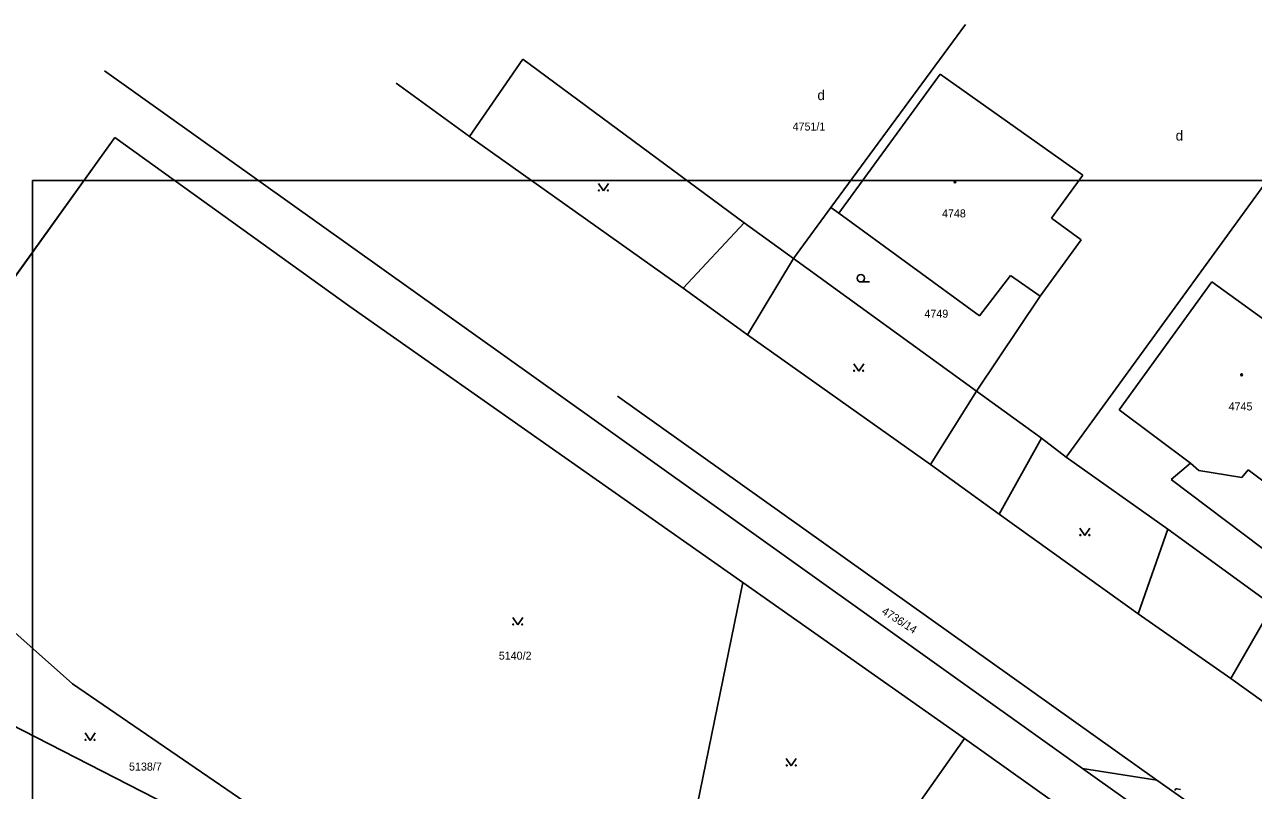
# Model space of a CAD drawing. Extents: x -400488 to -400124, y -1251493 to -1251223.
# Drawn here: x -400397.9 to -400324.2, y -1251269.6 to -1251223.7 of the extents above; entities that cross this region are included whole.
import ezdxf

# ---------------------------------------------------------------- set-up
doc = ezdxf.new("R2010")
doc.units = 0
doc.layers.add('Level 3', color=7, linetype='Continuous')
doc.layers.add('Level 63', color=7, linetype='Continuous')

msp = doc.modelspace()

# ---------------------------------------------------------------- linework, layer by layer
at = {"layer": 'Level 3'}
msp.add_lwpolyline([(-400397.431, -1251233.087), (-400250.431, -1251233.087), (-400250.431, -1251440.987), (-400397.431, -1251440.987)], close=True, dxfattribs=at)
at = {"layer": 'Level 63'}
for p, q in [((-400341.49, -1251223.74), (-400349.56, -1251234.71)), ((-400349.56, -1251234.71), (-400341.49, -1251223.74)), ((-400371.24, -1251230.44), (-400368.03, -1251225.82)), ((-400354.77, -1251235.63), (-400368.03, -1251225.82)), ((-400368.03, -1251225.82), (-400354.77, -1251235.63)), ((-400363.63, -1251247.54), (-400393.13, -1251226.52)), ((-400393.13, -1251226.52), (-400363.63, -1251247.54)), ((-400349.1, -1251235.04), (-400343.01, -1251226.71)), ((-400343.01, -1251226.71), (-400334.46, -1251232.77)), ((-400371.24, -1251230.44), (-400375.63, -1251227.25)), ((-400375.63, -1251227.25), (-400371.24, -1251230.44)), ((-400407.88, -1251251.89), (-400392.51, -1251230.5)), ((-400392.51, -1251230.5), (-400407.88, -1251251.89)), ((-400392.51, -1251230.5), (-400378.41, -1251240.64)), ((-400378.41, -1251240.64), (-400392.51, -1251230.5)), ((-400358.43, -1251239.54), (-400371.24, -1251230.44)), ((-400371.24, -1251230.44), (-400358.43, -1251239.54)), ((-400335.45, -1251249.68), (-400321.67, -1251230.69)), ((-400321.67, -1251230.69), (-400335.45, -1251249.68)), ((-400334.46, -1251232.77), (-400336.34, -1251235.35)), ((-400363.51, -1251233.26), (-400363.21, -1251233.71)), ((-400363.21, -1251233.71), (-400362.91, -1251233.26)), ((-400349.56, -1251234.71), (-400351.8, -1251237.76)), ((-400351.8, -1251237.76), (-400349.56, -1251234.71)), ((-400349.56, -1251234.71), (-400349.1, -1251235.04)), ((-400349.1, -1251235.04), (-400349.56, -1251234.71)), ((-400349.1, -1251235.04), (-400340.65, -1251241.2)), ((-400340.65, -1251241.2), (-400349.1, -1251235.04)), ((-400354.77, -1251235.63), (-400358.43, -1251239.54)), ((-400351.8, -1251237.76), (-400354.77, -1251235.63)), ((-400354.77, -1251235.63), (-400351.8, -1251237.76)), ((-400336.34, -1251235.35), (-400334.55, -1251236.65)), ((-400334.55, -1251236.65), (-400337.02, -1251240.03)), ((-400354.57, -1251242.34), (-400351.8, -1251237.76)), ((-400340.84, -1251245.72), (-400351.8, -1251237.76)), ((-400351.8, -1251237.76), (-400340.84, -1251245.72)), ((-400340.65, -1251241.2), (-400338.8, -1251238.78)), ((-400338.8, -1251238.78), (-400340.65, -1251241.2)), ((-400338.8, -1251238.78), (-400337.02, -1251240.03)), ((-400337.02, -1251240.03), (-400338.8, -1251238.78)), ((-400354.57, -1251242.34), (-400358.43, -1251239.54)), ((-400358.43, -1251239.54), (-400354.57, -1251242.34)), ((-400347.77, -1251239.17), (-400347.245, -1251239.17)), ((-400332.29, -1251246.83), (-400326.73, -1251239.16)), ((-400326.73, -1251239.16), (-400322.23, -1251242.42)), ((-400337.02, -1251240.03), (-400340.84, -1251245.72)), ((-400340.84, -1251245.72), (-400337.02, -1251240.03)), ((-400378.41, -1251240.64), (-400354.85, -1251257.19)), ((-400354.85, -1251257.19), (-400378.41, -1251240.64)), ((-400343.6, -1251250.12), (-400354.57, -1251242.34)), ((-400354.57, -1251242.34), (-400343.6, -1251250.12)), ((-400348.2, -1251244.07), (-400347.9, -1251244.52)), ((-400347.9, -1251244.52), (-400347.6, -1251244.07)), ((-400362.37, -1251246.01), (-400330.02, -1251269.03)), ((-400330.02, -1251269.03), (-400362.37, -1251246.01)), ((-400340.84, -1251245.72), (-400343.6, -1251250.12)), ((-400336.93, -1251248.53), (-400340.84, -1251245.72)), ((-400340.84, -1251245.72), (-400336.93, -1251248.53)), ((-400328, -1251250.04), (-400332.29, -1251246.83)), ((-400334.48, -1251268.34), (-400363.63, -1251247.54)), ((-400363.63, -1251247.54), (-400334.48, -1251268.34)), ((-400339.47, -1251253.09), (-400336.93, -1251248.53)), ((-400335.45, -1251249.68), (-400336.93, -1251248.53)), ((-400336.93, -1251248.53), (-400335.45, -1251249.68)), ((-400329.37, -1251253.99), (-400335.45, -1251249.68)), ((-400335.45, -1251249.68), (-400329.37, -1251253.99)), ((-400329.16, -1251251.02), (-400328, -1251250.04)), ((-400328, -1251250.04), (-400327.5, -1251250.48)), ((-400339.47, -1251253.09), (-400343.6, -1251250.12)), ((-400343.6, -1251250.12), (-400339.47, -1251253.09)), ((-400327.5, -1251250.48), (-400324.92, -1251250.9)), ((-400324.92, -1251250.9), (-400324.54, -1251250.43)), ((-400324.54, -1251250.43), (-400321.83, -1251252.48)), ((-400323.7, -1251255.12), (-400329.16, -1251251.02)), ((-400407.88, -1251251.89), (-400395.04, -1251263.25)), ((-400395.04, -1251263.25), (-400407.88, -1251251.89)), ((-400331.14, -1251259.06), (-400339.47, -1251253.09)), ((-400339.47, -1251253.09), (-400331.14, -1251259.06)), ((-400334.64, -1251253.92), (-400334.34, -1251254.37)), ((-400334.34, -1251254.37), (-400334.04, -1251253.92)), ((-400331.14, -1251259.06), (-400329.37, -1251253.99)), ((-400323.07, -1251258.57), (-400329.37, -1251253.99)), ((-400329.37, -1251253.99), (-400323.07, -1251258.57)), ((-400360.87, -1251286.63), (-400354.85, -1251257.19)), ((-400354.85, -1251257.19), (-400360.87, -1251286.63)), ((-400354.85, -1251257.19), (-400341.55, -1251266.53)), ((-400341.55, -1251266.53), (-400354.85, -1251257.19)), ((-400323.07, -1251258.57), (-400325.58, -1251262.94)), ((-400368.64, -1251259.28), (-400368.34, -1251259.73)), ((-400368.34, -1251259.73), (-400368.04, -1251259.28)), ((-400325.58, -1251262.94), (-400331.14, -1251259.06)), ((-400331.14, -1251259.06), (-400325.58, -1251262.94)), ((-400395.04, -1251263.25), (-400369.97, -1251280.4)), ((-400369.97, -1251280.4), (-400395.04, -1251263.25)), ((-400308.26, -1251275.37), (-400325.58, -1251262.94)), ((-400325.58, -1251262.94), (-400308.26, -1251275.37)), ((-400401.86, -1251264.1), (-400369.97, -1251280.4)), ((-400369.97, -1251280.4), (-400401.86, -1251264.1)), ((-400394.29, -1251266.2), (-400393.99, -1251266.65)), ((-400393.99, -1251266.65), (-400393.69, -1251266.2)), ((-400357.4, -1251289), (-400341.55, -1251266.53)), ((-400341.55, -1251266.53), (-400357.4, -1251289)), ((-400341.55, -1251266.53), (-400302.68, -1251294.16)), ((-400302.68, -1251294.16), (-400341.55, -1251266.53)), ((-400352.24, -1251267.73), (-400351.94, -1251268.18)), ((-400351.94, -1251268.18), (-400351.64, -1251267.73)), ((-400330.02, -1251269.03), (-400334.48, -1251268.34)), ((-400334.48, -1251268.34), (-400330.02, -1251269.03)), ((-400331.17, -1251270.69), (-400334.48, -1251268.34)), ((-400330.02, -1251269.03), (-400327.86, -1251270.56)), ((-400328.813, -1251269.554), (-400328.595, -1251269.602))]:
    msp.add_line(p, q, dxfattribs=at)
for centre, radius in [((-400363.48, -1251233.68), 0.03), ((-400362.94, -1251233.68), 0.03), ((-400342.13, -1251233.166), 0.054), ((-400347.77, -1251238.945), 0.225), ((-400348.17, -1251244.49), 0.03), ((-400347.63, -1251244.49), 0.03), ((-400324.94, -1251244.736), 0.054), ((-400334.61, -1251254.34), 0.03), ((-400334.07, -1251254.34), 0.03), ((-400368.61, -1251259.7), 0.03), ((-400368.07, -1251259.7), 0.03), ((-400394.26, -1251266.62), 0.03), ((-400393.72, -1251266.62), 0.03), ((-400352.21, -1251268.15), 0.03), ((-400351.67, -1251268.15), 0.03)]:
    msp.add_circle(centre, radius, dxfattribs=at)
msp.add_arc((-400328.834, -1251269.652), 0.1, 77.75266, 177.76308, dxfattribs=at)

# ---------------------------------------------------------------- texts
for s, height, p in [('d', 0.6, (-400350.373, -1251228.27)), ('4751/1', 0.48, (-400351.862, -1251230.09)), ('d', 0.6, (-400328.893, -1251230.69)), ('4748', 0.48, (-400342.904, -1251235.3)), ('4745', 0.48, (-400325.72, -1251246.87)), ('5140/2', 0.48, (-400369.48, -1251261.81)), ('5138/7', 0.48, (-400391.652, -1251268.46))]:
    msp.add_text(s, height=height, dxfattribs=at).set_placement(p)
for s, rotation, p in [('4749', 0.01, (-400343.957, -1251241.31)), ('4736/14', 327.3121, (-400346.562, -1251259.024))]:
    msp.add_text(s, height=0.48, rotation=rotation, dxfattribs=at).set_placement(p)

doc.saveas('drawing.dxf')
